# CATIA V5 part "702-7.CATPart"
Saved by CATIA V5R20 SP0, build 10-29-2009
Part number: 702-7
Source: Unknown
Property "ARTICLENO": "702-7"
Property "BOMINFO": "702-7"
Property "CODE": "702-7"
Property "L": "250.000"
Property "LINA": "702-7"
Property "NB": "702-7"
Property "NBSYN": "$CODE."
Property "NN": "702"
Property "SUPPLIER": "CF"
Bounding box of the stored display mesh (mm): x -107 to 0, y 0 to 250, z -15 to 15
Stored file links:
  C:\Users\Utente\Desktop\3D files 702\702-7.CATPart
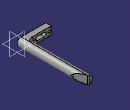
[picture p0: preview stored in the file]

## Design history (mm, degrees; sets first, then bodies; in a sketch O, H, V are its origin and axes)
Body1 "Geometry.1" (main body)
  Solid1 "702-7.catpart": solid without history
